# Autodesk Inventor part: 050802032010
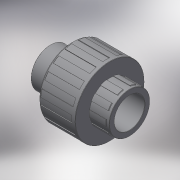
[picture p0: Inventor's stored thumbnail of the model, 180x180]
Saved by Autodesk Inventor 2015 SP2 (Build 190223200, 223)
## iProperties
Created: 2017-10
Part Number: 050802032010
Material: Generic
Description: PLASSON UNION+O RING THR-CEM 32-1
Document SubType Name: Modeling
Designer: KIM
Density: 1 g/cm^3
Appearance: Default
Author: KIM
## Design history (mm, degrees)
derived "050802.ipt"
feature "Solid1::050802.ipt"
tag "TaggingFeature1"
body "Solid1"
other parameters: "d0" = 57, "d3" = 32, "d4" = 30.291, "d5" = 38.4, "d7" = 40.96, "d8" = 59, "d9" = 22, "d11" = 27.2, "d12" = 30.4, "d14" = 15, "d15" = 16.5, "d16" = 13.5, "d17" = 2, "d19" = 57.82, "d20" = 2.2, "d21" = 1.77, "d25" = 5.9, "d26" = 2.95, "d27" = 20.97, "d28" = 0, "d32" = 5.9, "d33" = 2.95, "d35" = 0, "d39" = 0.32, "d45" = 0.48, "d49" = 360 deg, "d51" = 0.59, "d55" = 360 deg, "d_" = 32, "E_" = 59, "H_" = 39, "l_" = 22, "Z_" = 11, "G_" = 30.291, "d13" = 15, "d24" = 23.3, "d40" = 0.48, "d44" = 0.59
